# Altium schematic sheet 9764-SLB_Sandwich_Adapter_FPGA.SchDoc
size B
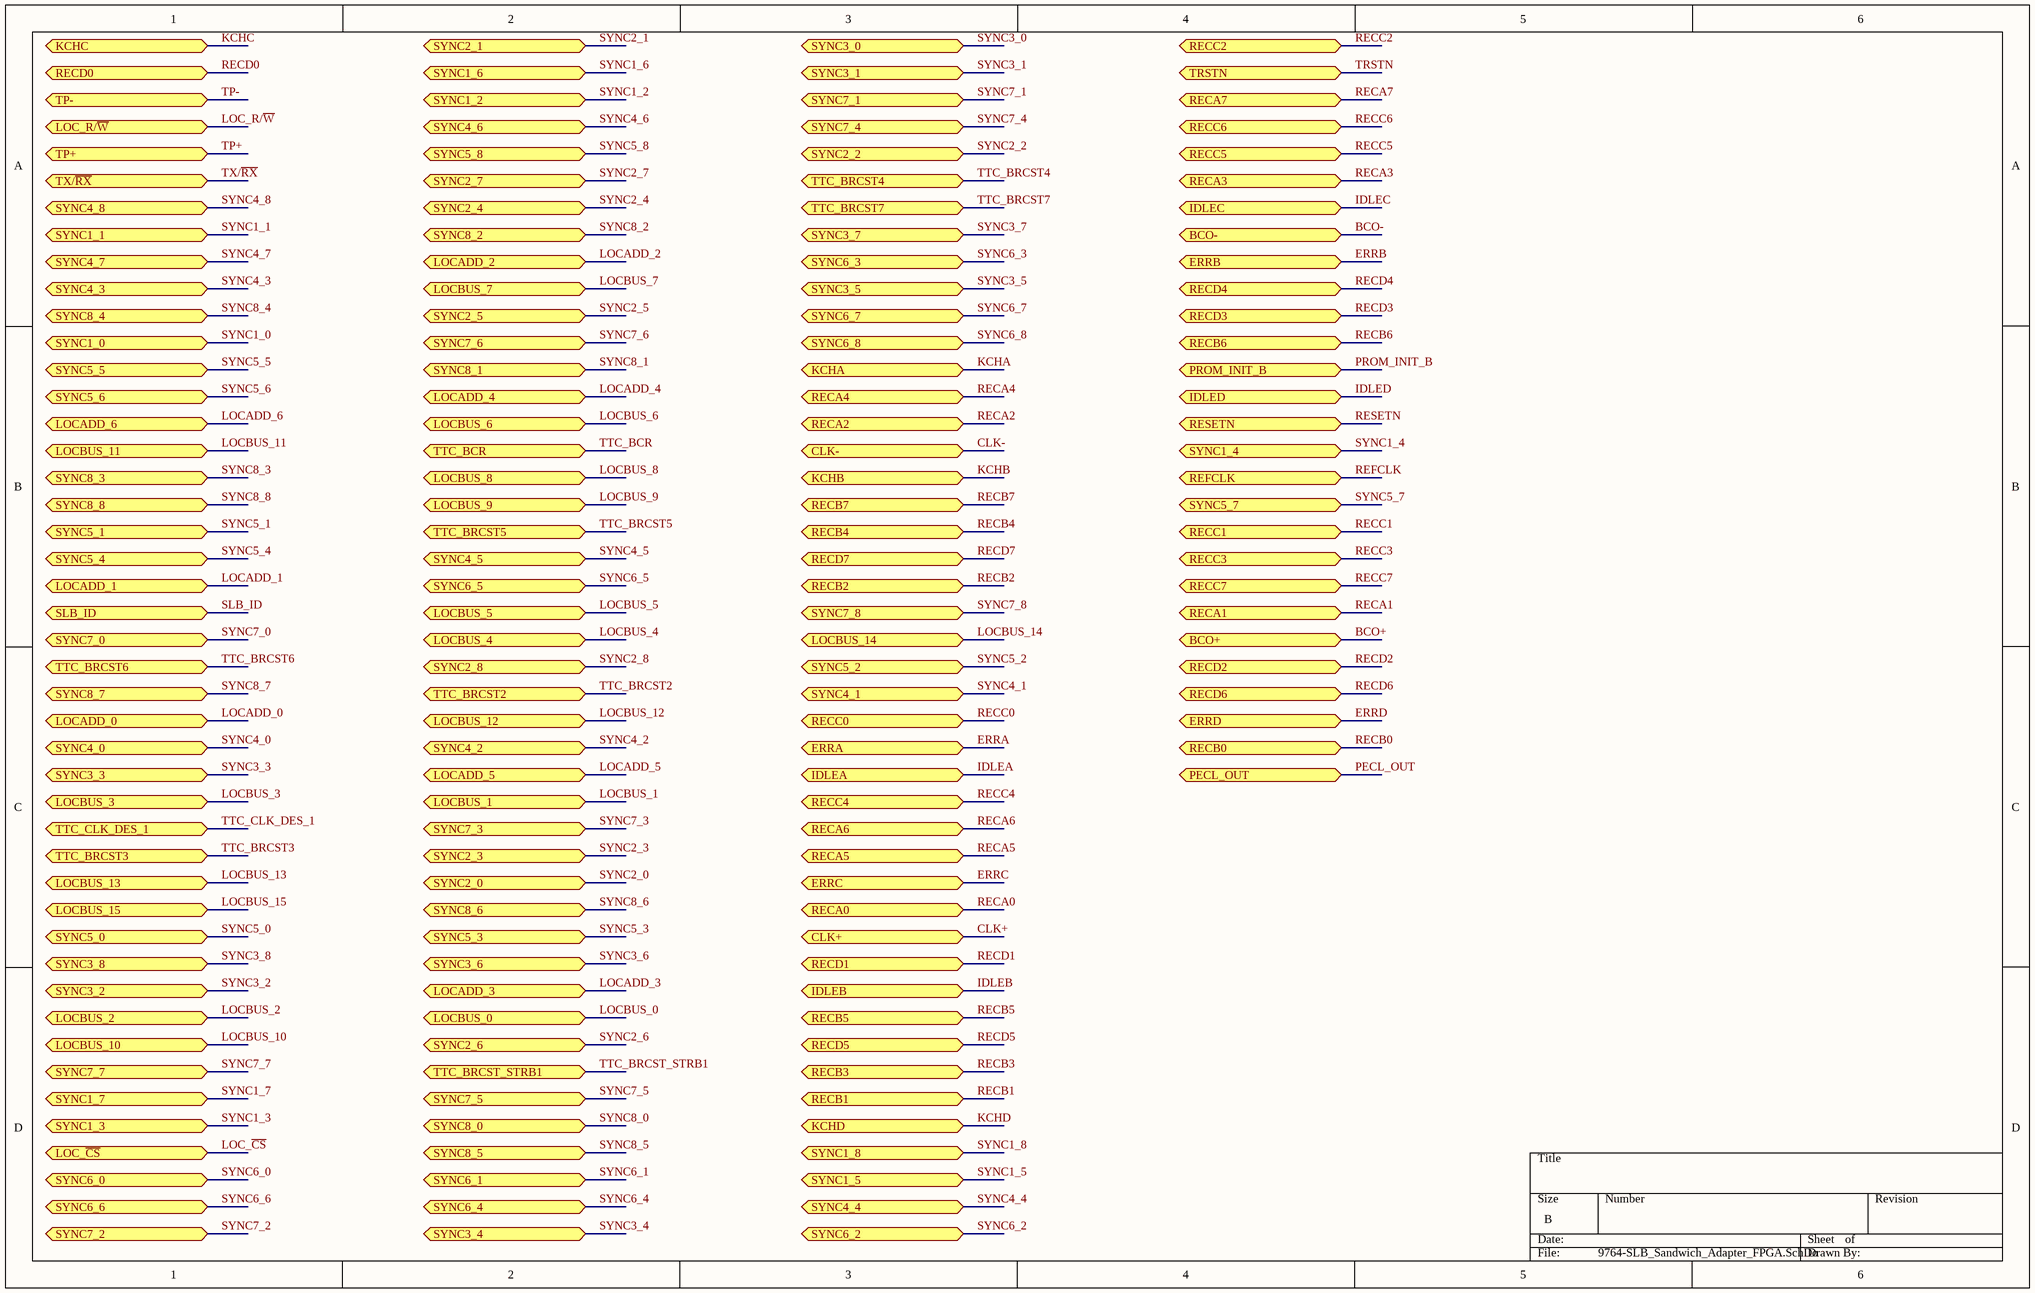
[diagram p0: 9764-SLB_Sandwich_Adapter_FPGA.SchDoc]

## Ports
BCO+ (bidir), BCO- (bidir), CLK+ (bidir), CLK- (bidir), ERRA (bidir), ERRB (bidir), ERRC (bidir), ERRD (bidir), IDLEA (bidir), IDLEB (bidir), IDLEC (bidir), IDLED (bidir), KCHA (bidir), KCHB (bidir), KCHC (bidir), KCHD (bidir), LOC_R/~{W} (bidir), LOC_~{CS} (bidir), LOCADD_0 (bidir), LOCADD_1 (bidir), LOCADD_2 (bidir), LOCADD_3 (bidir), LOCADD_4 (bidir), LOCADD_5 (bidir), LOCADD_6 (bidir), LOCBUS_0 (bidir), LOCBUS_1 (bidir), LOCBUS_2 (bidir), LOCBUS_3 (bidir), LOCBUS_4 (bidir), LOCBUS_5 (bidir), LOCBUS_6 (bidir), LOCBUS_7 (bidir), LOCBUS_8 (bidir), LOCBUS_9 (bidir), LOCBUS_10 (bidir), LOCBUS_11 (bidir), LOCBUS_12 (bidir), LOCBUS_13 (bidir), LOCBUS_14 (bidir), LOCBUS_15 (bidir), PECL_OUT (bidir), PROM_INIT_B (bidir), RECA0 (bidir), RECA1 (bidir), RECA2 (bidir), RECA3 (bidir), RECA4 (bidir), RECA5 (bidir), RECA6 (bidir), RECA7 (bidir), RECB0 (bidir), RECB1 (bidir), RECB2 (bidir), RECB3 (bidir), RECB4 (bidir), RECB5 (bidir), RECB6 (bidir), RECB7 (bidir), RECC0 (bidir), RECC1 (bidir), RECC2 (bidir), RECC3 (bidir), RECC4 (bidir), RECC5 (bidir), RECC6 (bidir), RECC7 (bidir), RECD0 (bidir), RECD1 (bidir), RECD2 (bidir), RECD3 (bidir), RECD4 (bidir), RECD5 (bidir), RECD6 (bidir), RECD7 (bidir), REFCLK (bidir), RESETN (bidir), SLB_ID (bidir), SYNC1_0 (bidir), SYNC1_1 (bidir), SYNC1_2 (bidir), SYNC1_3 (bidir), SYNC1_4 (bidir), SYNC1_5 (bidir), SYNC1_6 (bidir), SYNC1_7 (bidir), SYNC1_8 (bidir), SYNC2_0 (bidir), SYNC2_1 (bidir), SYNC2_2 (bidir), SYNC2_3 (bidir), SYNC2_4 (bidir), SYNC2_5 (bidir), SYNC2_6 (bidir), SYNC2_7 (bidir), SYNC2_8 (bidir), SYNC3_0 (bidir), SYNC3_1 (bidir), SYNC3_2 (bidir), SYNC3_3 (bidir), SYNC3_4 (bidir), SYNC3_5 (bidir), SYNC3_6 (bidir), SYNC3_7 (bidir), SYNC3_8 (bidir), SYNC4_0 (bidir), SYNC4_1 (bidir), SYNC4_2 (bidir), SYNC4_3 (bidir), SYNC4_4 (bidir), SYNC4_5 (bidir), SYNC4_6 (bidir), SYNC4_7 (bidir), SYNC4_8 (bidir), SYNC5_0 (bidir), SYNC5_1 (bidir), SYNC5_2 (bidir), SYNC5_3 (bidir), SYNC5_4 (bidir), SYNC5_5 (bidir), SYNC5_6 (bidir), SYNC5_7 (bidir), SYNC5_8 (bidir), SYNC6_0 (bidir), SYNC6_1 (bidir), SYNC6_2 (bidir), SYNC6_3 (bidir), SYNC6_4 (bidir), SYNC6_5 (bidir), SYNC6_6 (bidir), SYNC6_7 (bidir), SYNC6_8 (bidir), SYNC7_0 (bidir), SYNC7_1 (bidir), SYNC7_2 (bidir), SYNC7_3 (bidir), SYNC7_4 (bidir), SYNC7_5 (bidir), SYNC7_6 (bidir), SYNC7_7 (bidir), SYNC7_8 (bidir), SYNC8_0 (bidir), SYNC8_1 (bidir), SYNC8_2 (bidir), SYNC8_3 (bidir), SYNC8_4 (bidir), SYNC8_5 (bidir), SYNC8_6 (bidir), SYNC8_7 (bidir), SYNC8_8 (bidir), TP+ (bidir), TP- (bidir), TRSTN (bidir), TTC_BCR (bidir), TTC_BRCST2 (bidir), TTC_BRCST3 (bidir), TTC_BRCST4 (bidir), TTC_BRCST5 (bidir), TTC_BRCST6 (bidir), TTC_BRCST7 (bidir), TTC_BRCST_STRB1 (bidir), TTC_CLK_DES_1 (bidir), TX/~{RX} (bidir)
